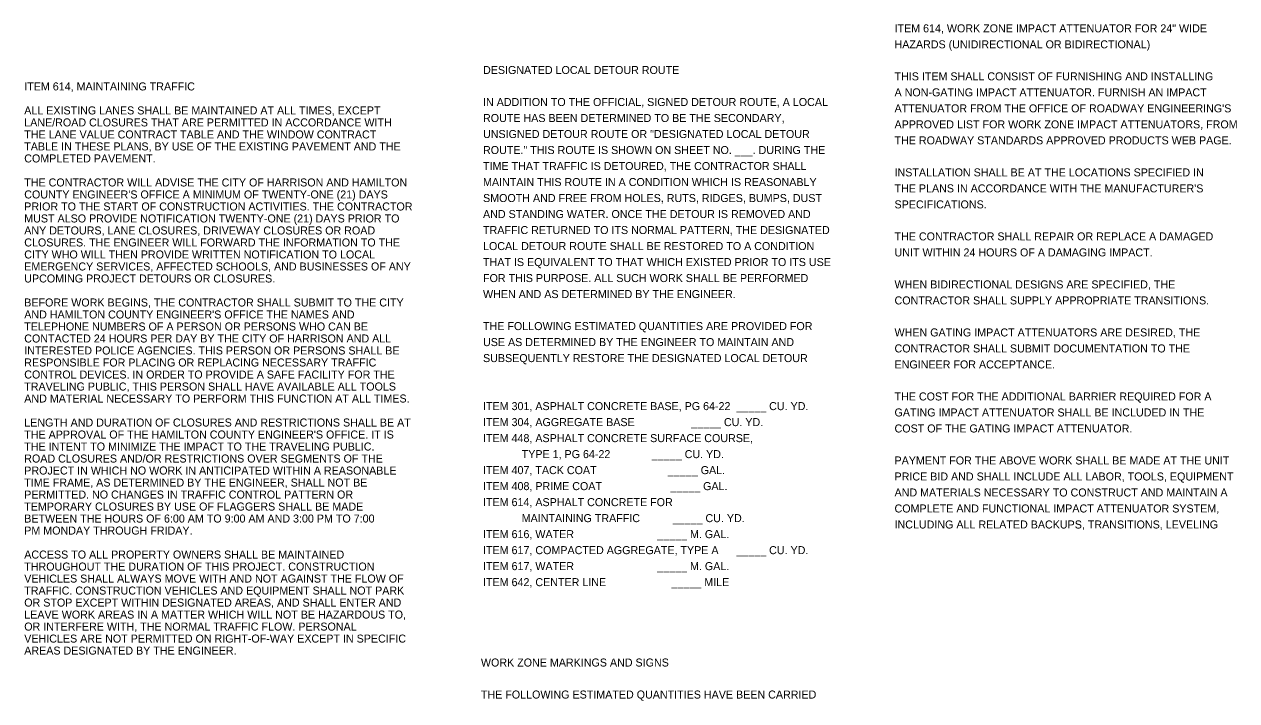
# Model space of a CAD drawing. Extents: x -65.5 to 34, y -24.3 to 23.1.
# Drawn here: x -65.21 to -44.01, y 10.7 to 22.54 of the extents above; entities that cross this region are included whole.
import ezdxf

# ---------------------------------------------------------------- set-up
doc = ezdxf.new("R2010")
doc.units = 0
doc.layers.add('SH_Text', color=7, linetype='Continuous')

msp = doc.modelspace()

# ---------------------------------------------------------------- texts
at = {"layer": 'SH_Text'}
for s, p in [('ITEM 614, WORK ZONE IMPACT ATTENUATOR FOR 24" WIDE', (-49.991, 22.397)), ('HAZARDS (UNIDIRECTIONAL OR BIDIRECTIONAL)', (-49.991, 22.117)), ('DESIGNATED LOCAL DETOUR ROUTE', (-57.189, 21.668)), ('THIS ITEM SHALL CONSIST OF FURNISHING AND INSTALLING', (-49.991, 21.557)), ('ITEM 614, MAINTAINING TRAFFIC', (-65.214, 21.381)), ('IN ADDITION TO THE OFFICIAL, SIGNED DETOUR ROUTE, A LOCAL', (-57.189, 21.108)), ('A NON-GATING IMPACT ATTENUATOR. FURNISH AN IMPACT', (-49.991, 21.277)), ('ALL EXISTING LANES SHALL BE MAINTAINED AT ALL TIMES, EXCEPT ', (-65.214, 20.961)), ("ATTENUATOR FROM THE OFFICE OF ROADWAY ENGINEERING'S", (-49.991, 20.997)), ('LANE/ROAD CLOSURES THAT ARE PERMITTED IN ACCORDANCE WITH ', (-65.214, 20.751)), ('ROUTE HAS BEEN DETERMINED TO BE THE SECONDARY,', (-57.189, 20.828)), ('APPROVED LIST FOR WORK ZONE IMPACT ATTENUATORS, FROM', (-49.991, 20.717)), ('THE LANE VALUE CONTRACT TABLE AND THE WINDOW CONTRACT ', (-65.214, 20.541)), ('UNSIGNED DETOUR ROUTE OR "DESIGNATED LOCAL DETOUR', (-57.189, 20.548)), ('THE ROADWAY STANDARDS APPROVED PRODUCTS WEB PAGE.', (-49.991, 20.437)), ('TABLE IN THESE PLANS, BY USE OF THE EXISTING PAVEMENT AND THE ', (-65.214, 20.331)), ('ROUTE." THIS ROUTE IS SHOWN ON SHEET NO. ___. DURING THE', (-57.189, 20.268)), ('COMPLETED PAVEMENT.', (-65.214, 20.121)), ('TIME THAT TRAFFIC IS DETOURED, THE CONTRACTOR SHALL', (-57.189, 19.988)), ('INSTALLATION SHALL BE AT THE LOCATIONS SPECIFIED IN', (-49.991, 19.877)), ('THE CONTRACTOR WILL ADVISE THE CITY OF HARRISON AND HAMILTON ', (-65.214, 19.701)), ('MAINTAIN THIS ROUTE IN A CONDITION WHICH IS REASONABLY', (-57.189, 19.708)), ("THE PLANS IN ACCORDANCE WITH THE MANUFACTURER'S", (-49.991, 19.597)), ("COUNTY ENGINEER'S OFFICE A MINIMUM OF TWENTY-ONE (21) DAYS ", (-65.214, 19.491)), ('SMOOTH AND FREE FROM HOLES, RUTS, RIDGES, BUMPS, DUST', (-57.189, 19.428)), ('PRIOR TO THE START OF CONSTRUCTION ACTIVITIES. THE CONTRACTOR ', (-65.214, 19.281)), ('SPECIFICATIONS.', (-49.991, 19.317)), ('MUST ALSO PROVIDE NOTIFICATION TWENTY-ONE (21) DAYS PRIOR TO ', (-65.214, 19.071)), ('AND STANDING WATER. ONCE THE DETOUR IS REMOVED AND', (-57.189, 19.148)), ('ANY DETOURS, LANE CLOSURES, DRIVEWAY CLOSURES OR ROAD ', (-65.214, 18.861)), ('TRAFFIC RETURNED TO ITS NORMAL PATTERN, THE DESIGNATED', (-57.189, 18.868)), ('THE CONTRACTOR SHALL REPAIR OR REPLACE A DAMAGED', (-49.991, 18.757)), ('CLOSURES. THE ENGINEER WILL FORWARD THE INFORMATION TO THE ', (-65.214, 18.651)), ('LOCAL DETOUR ROUTE SHALL BE RESTORED TO A CONDITION', (-57.189, 18.588)), ('CITY WHO WILL THEN PROVIDE WRITTEN NOTIFICATION TO LOCAL ', (-65.214, 18.441)), ('UNIT WITHIN 24 HOURS OF A DAMAGING IMPACT.', (-49.991, 18.477)), ('EMERGENCY SERVICES, AFFECTED SCHOOLS, AND BUSINESSES OF ANY ', (-65.214, 18.231)), ('THAT IS EQUIVALENT TO THAT WHICH EXISTED PRIOR TO ITS USE', (-57.189, 18.308)), ('UPCOMING PROJECT DETOURS OR CLOSURES. ', (-65.214, 18.021)), ('FOR THIS PURPOSE. ALL SUCH WORK SHALL BE PERFORMED', (-57.189, 18.028)), ('WHEN BIDIRECTIONAL DESIGNS ARE SPECIFIED, THE', (-49.991, 17.917)), ('WHEN AND AS DETERMINED BY THE ENGINEER.', (-57.189, 17.748)), ('BEFORE WORK BEGINS, THE CONTRACTOR SHALL SUBMIT TO THE CITY ', (-65.214, 17.601)), ('CONTRACTOR SHALL SUPPLY APPROPRIATE TRANSITIONS.', (-49.991, 17.637)), ("AND HAMILTON COUNTY ENGINEER'S OFFICE THE NAMES AND ", (-65.214, 17.391)), ('TELEPHONE NUMBERS OF A PERSON OR PERSONS WHO CAN BE ', (-65.214, 17.181)), ('THE FOLLOWING ESTIMATED QUANTITIES ARE PROVIDED FOR', (-57.189, 17.188)), ('WHEN GATING IMPACT ATTENUATORS ARE DESIRED, THE', (-49.991, 17.077)), ('CONTACTED 24 HOURS PER DAY BY THE CITY OF HARRISON AND ALL ', (-65.214, 16.971)), ('USE AS DETERMINED BY THE ENGINEER TO MAINTAIN AND', (-57.189, 16.908)), ('INTERESTED POLICE AGENCIES. THIS PERSON OR PERSONS SHALL BE ', (-65.214, 16.761)), ('SUBSEQUENTLY RESTORE THE DESIGNATED LOCAL DETOUR', (-57.189, 16.628)), ('CONTRACTOR SHALL SUBMIT DOCUMENTATION TO THE', (-49.991, 16.797)), ('RESPONSIBLE FOR PLACING OR REPLACING NECESSARY TRAFFIC ', (-65.214, 16.551)), ('ENGINEER FOR ACCEPTANCE.', (-49.991, 16.517)), ('CONTROL DEVICES. IN ORDER TO PROVIDE A SAFE FACILITY FOR THE ', (-65.214, 16.341)), ('TRAVELING PUBLIC, THIS PERSON SHALL HAVE AVAILABLE ALL TOOLS ', (-65.214, 16.131)), ('AND MATERIAL NECESSARY TO PERFORM THIS FUNCTION AT ALL TIMES. ', (-65.214, 15.921)), ('ITEM 301, ASPHALT CONCRETE BASE, PG 64-22  _____ CU. YD.', (-57.189, 15.788)), ('THE COST FOR THE ADDITIONAL BARRIER REQUIRED FOR A', (-49.991, 15.957)), ('GATING IMPACT ATTENUATOR SHALL BE INCLUDED IN THE', (-49.991, 15.677)), ('LENGTH AND DURATION OF CLOSURES AND RESTRICTIONS SHALL BE AT ', (-65.214, 15.501)), ('ITEM 304, AGGREGATE BASE                   _____ CU. YD.', (-57.189, 15.508)), ('COST OF THE GATING IMPACT ATTENUATOR.', (-49.991, 15.397)), ("THE APPROVAL OF THE HAMILTON COUNTY ENGINEER'S OFFICE. IT IS ", (-65.214, 15.291)), ('ITEM 448, ASPHALT CONCRETE SURFACE COURSE,', (-57.189, 15.228)), ('THE INTENT TO MINIMIZE THE IMPACT TO THE TRAVELING PUBLIC. ', (-65.214, 15.081)), ('             TYPE 1, PG 64-22              _____ CU. YD.', (-57.189, 14.948)), ('ROAD CLOSURES AND/OR RESTRICTIONS OVER SEGMENTS OF THE ', (-65.214, 14.871)), ('PAYMENT FOR THE ABOVE WORK SHALL BE MADE AT THE UNIT', (-49.991, 14.837)), ('PROJECT IN WHICH NO WORK IN ANTICIPATED WITHIN A REASONABLE ', (-65.214, 14.661)), ('ITEM 407, TACK COAT                        _____ GAL.', (-57.189, 14.668)), ('PRICE BID AND SHALL INCLUDE ALL LABOR, TOOLS, EQUIPMENT', (-49.991, 14.557)), ('TIME FRAME, AS DETERMINED BY THE ENGINEER, SHALL NOT BE ', (-65.214, 14.451)), ('ITEM 408, PRIME COAT                       _____ GAL.', (-57.189, 14.388)), ('PERMITTED. NO CHANGES IN TRAFFIC CONTROL PATTERN OR ', (-65.214, 14.241)), ('ITEM 614, ASPHALT CONCRETE FOR', (-57.189, 14.108)), ('AND MATERIALS NECESSARY TO CONSTRUCT AND MAINTAIN A', (-49.991, 14.277)), ('TEMPORARY CLOSURES BY USE OF FLAGGERS SHALL BE MADE ', (-65.214, 14.031)), ('COMPLETE AND FUNCTIONAL IMPACT ATTENUATOR SYSTEM,', (-49.991, 13.997)), ('BETWEEN THE HOURS OF 6:00 AM TO 9:00 AM AND 3:00 PM TO 7:00 ', (-65.214, 13.821)), ('             MAINTAINING TRAFFIC           _____ CU. YD.', (-57.189, 13.828)), ('INCLUDING ALL RELATED BACKUPS, TRANSITIONS, LEVELING', (-49.991, 13.717)), ('PM MONDAY THROUGH FRIDAY. ', (-65.214, 13.611)), ('ITEM 616, WATER                            _____ M. GAL.', (-57.189, 13.548)), ('ITEM 617, COMPACTED AGGREGATE, TYPE A      _____ CU. YD.', (-57.189, 13.268)), ('ACCESS TO ALL PROPERTY OWNERS SHALL BE MAINTAINED ', (-65.214, 13.191)), ('THROUGHOUT THE DURATION OF THIS PROJECT. CONSTRUCTION ', (-65.214, 12.981)), ('ITEM 617, WATER                            _____ M. GAL.', (-57.189, 12.988)), ('VEHICLES SHALL ALWAYS MOVE WITH AND NOT AGAINST THE FLOW OF ', (-65.214, 12.771)), ('ITEM 642, CENTER LINE                      _____ MILE', (-57.189, 12.708)), ('TRAFFIC. CONSTRUCTION VEHICLES AND EQUIPMENT SHALL NOT PARK ', (-65.214, 12.561)), ('OR STOP EXCEPT WITHIN DESIGNATED AREAS, AND SHALL ENTER AND ', (-65.214, 12.351)), ('LEAVE WORK AREAS IN A MATTER WHICH WILL NOT BE HAZARDOUS TO, ', (-65.214, 12.141)), ('OR INTERFERE WITH, THE NORMAL TRAFFIC FLOW. PERSONAL ', (-65.214, 11.931)), ('VEHICLES ARE NOT PERMITTED ON RIGHT-OF-WAY EXCEPT IN SPECIFIC ', (-65.214, 11.721)), ('AREAS DESIGNATED BY THE ENGINEER. ', (-65.214, 11.511)), ('WORK ZONE MARKINGS AND SIGNS', (-57.226, 11.302)), ('THE FOLLOWING ESTIMATED QUANTITIES HAVE BEEN CARRIED', (-57.226, 10.742))]:
    msp.add_text(s, height=0.14, dxfattribs=at).set_placement(p)

doc.saveas('drawing.dxf')
